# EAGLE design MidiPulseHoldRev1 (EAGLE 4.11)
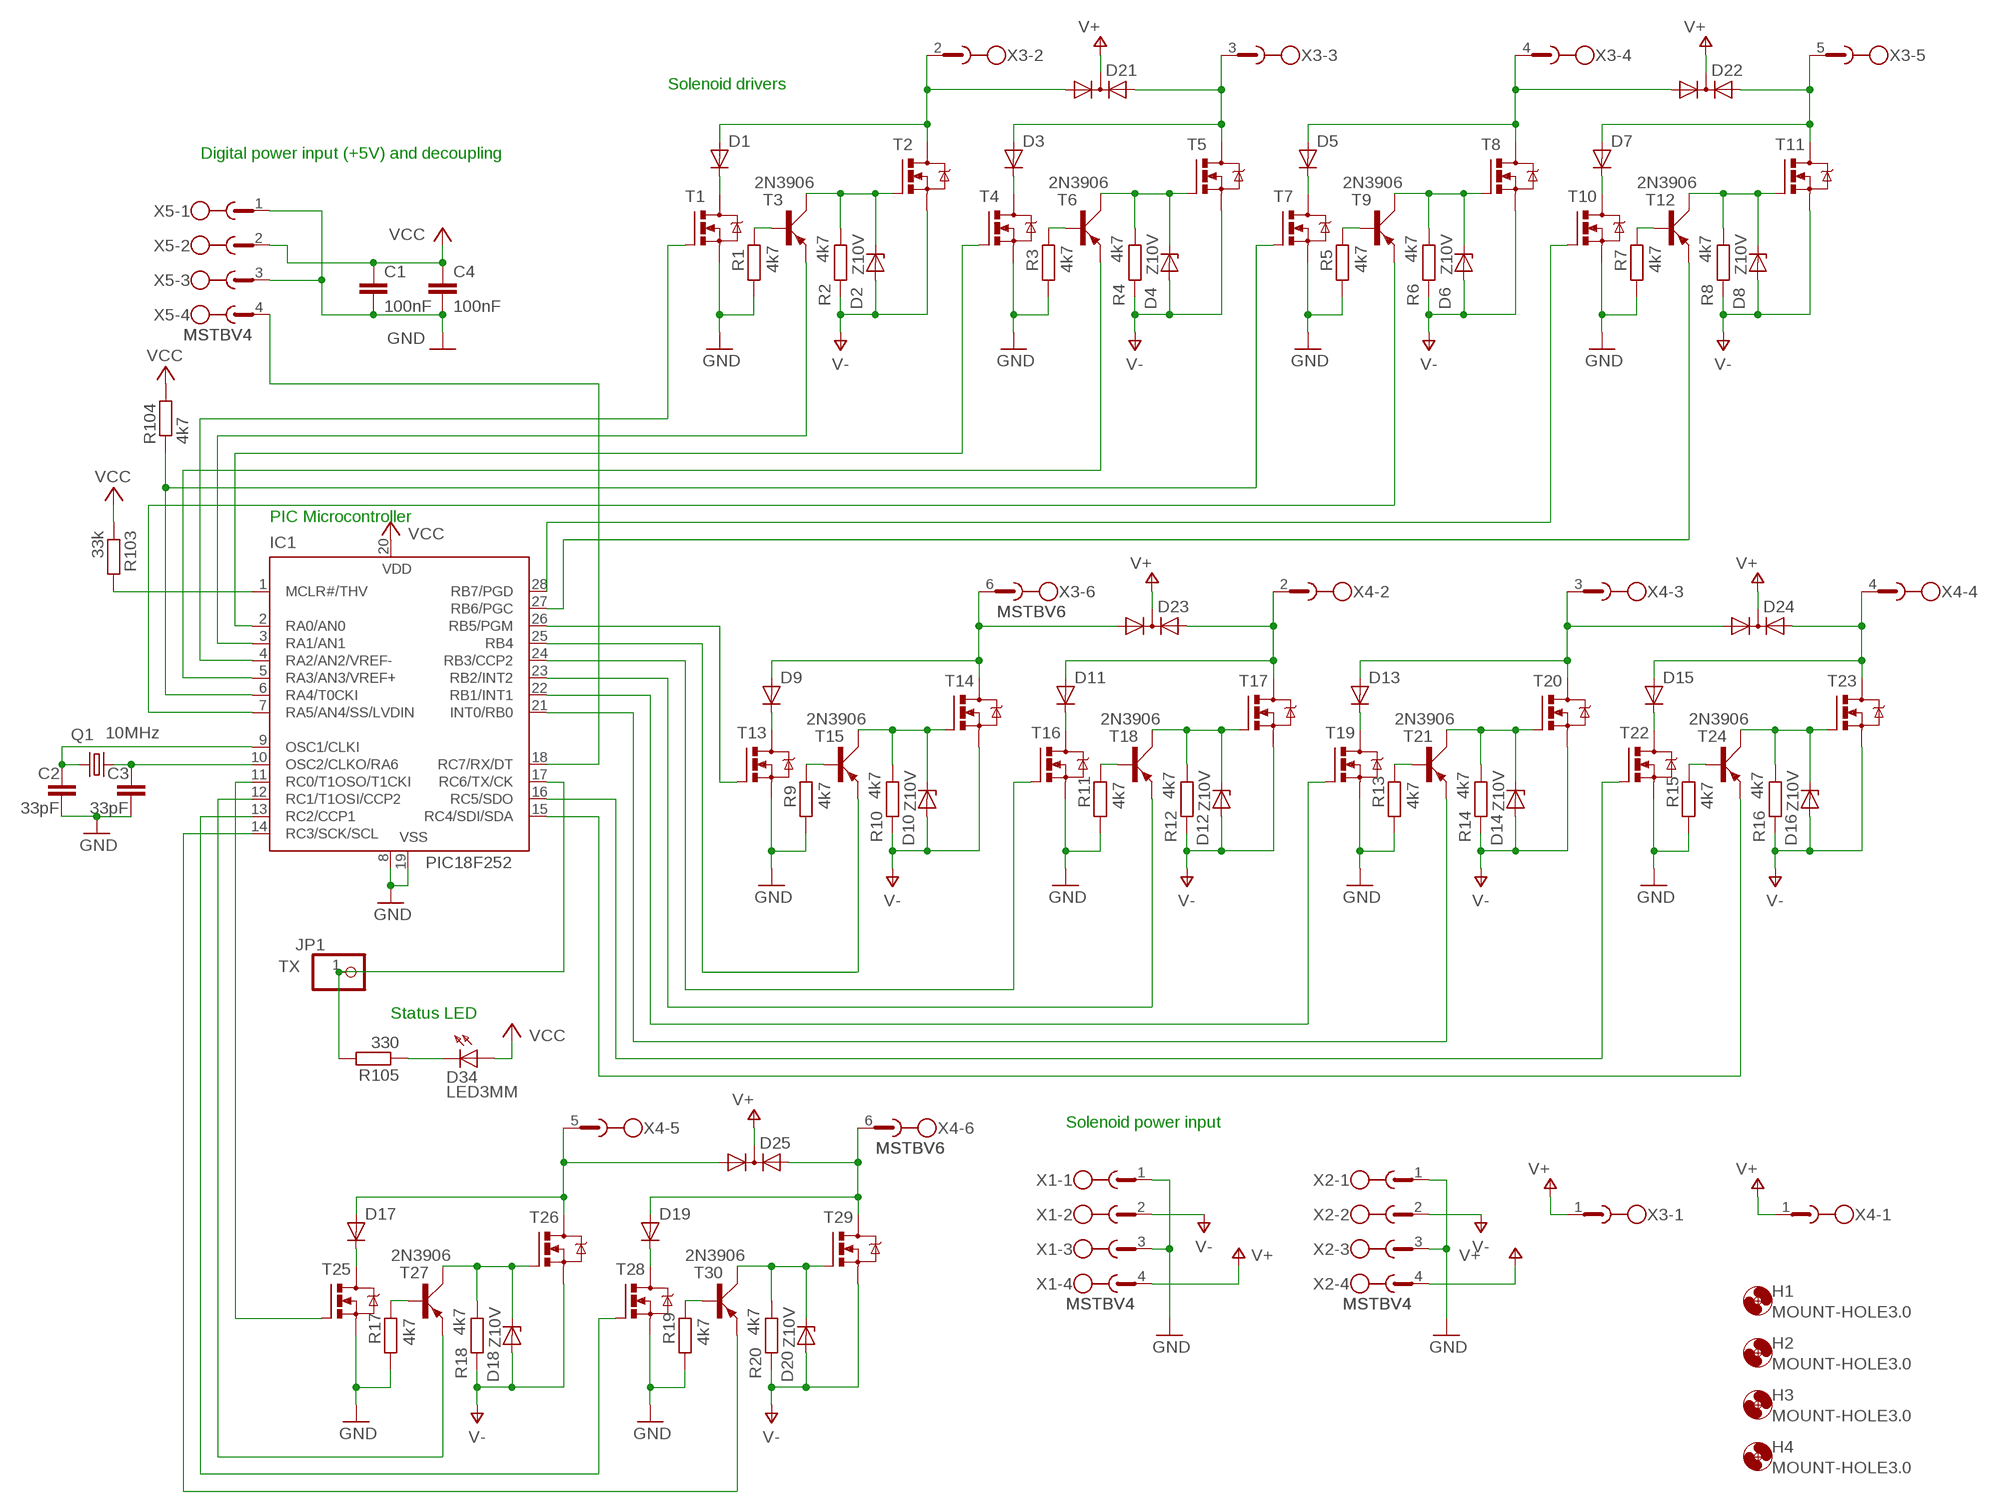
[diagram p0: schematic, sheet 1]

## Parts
C1  100nF  C-EU050-030X075  [C050-030X075]
C2  33pF  C-EU050-025X075  [C050-025X075]
C3  33pF  C-EU050-025X075  [C050-025X075]
C4  100nF  C-EU050-030X075  [C050-030X075]
D1  DIODE-P6-15  [P6-15]
D2  Z10V  ZENER-DIODEDO34-7  [DO34Z7]
D3  DIODE-P6-15  [P6-15]
D4  Z10V  ZENER-DIODEDO34-7  [DO34Z7]
D5  DIODE-P6-15  [P6-15]
D6  Z10V  ZENER-DIODEDO34-7  [DO34Z7]
D7  DIODE-P6-15  [P6-15]
D8  Z10V  ZENER-DIODEDO34-7  [DO34Z7]
D9  DIODE-P6-15  [P6-15]
D10  Z10V  ZENER-DIODEDO34-7  [DO34Z7]
D11  DIODE-P6-15  [P6-15]
D12  Z10V  ZENER-DIODEDO34-7  [DO34Z7]
D13  DIODE-P6-15  [P6-15]
D14  Z10V  ZENER-DIODEDO34-7  [DO34Z7]
D15  DIODE-P6-15  [P6-15]
D16  Z10V  ZENER-DIODEDO34-7  [DO34Z7]
D17  DIODE-P6-15  [P6-15]
D18  Z10V  ZENER-DIODEDO34-7  [DO34Z7]
D19  DIODE-P6-15  [P6-15]
D20  Z10V  ZENER-DIODEDO34-7  [DO34Z7]
D21  DIODE-2AC|CATO220V  [TO220ABS]
D22  DIODE-2AC|CATO220V  [TO220ABS]
D23  DIODE-2AC|CATO220V  [TO220ABS]
D24  DIODE-2AC|CATO220V  [TO220ABS]
D25  DIODE-2AC|CATO220V  [TO220ABS]
D34  LED3MM  [LED3MM]
H1  MOUNT-HOLE3.0  [3,0]
H2  MOUNT-HOLE3.0  [3,0]
H3  MOUNT-HOLE3.0  [3,0]
H4  MOUNT-HOLE3.0  [3,0]
IC1  PIC18F252  [DIL28-3]
JP1  TX  PINHD-1X1  [1X01]
Q1  10MHz  HC49U70  [HC49U70]
R1  4k7  R-EU_0204/7  [0204/7]
R2  4k7  R-EU_0204/7  [0204/7]
R3  4k7  R-EU_0204/7  [0204/7]
R4  4k7  R-EU_0204/7  [0204/7]
R5  4k7  R-EU_0204/7  [0204/7]
R6  4k7  R-EU_0204/7  [0204/7]
R7  4k7  R-EU_0204/7  [0204/7]
R8  4k7  R-EU_0204/7  [0204/7]
R9  4k7  R-EU_0204/7  [0204/7]
R10  4k7  R-EU_0204/7  [0204/7]
R11  4k7  R-EU_0204/7  [0204/7]
R12  4k7  R-EU_0204/7  [0204/7]
R13  4k7  R-EU_0204/7  [0204/7]
R14  4k7  R-EU_0204/7  [0204/7]
R15  4k7  R-EU_0204/7  [0204/7]
R16  4k7  R-EU_0204/7  [0204/7]
R17  4k7  R-EU_0204/7  [0204/7]
R18  4k7  R-EU_0204/7  [0204/7]
R19  4k7  R-EU_0204/7  [0204/7]
R20  4k7  R-EU_0204/7  [0204/7]
R103  33k  R-EU_0207/10  [0207/10]
R104  4k7  R-EU_0207/10  [0207/10]
R105  330  R-EU_0207/7  [0207/7]
T1  IRF520  [TO220BV-ROUND]
T2  IRF520  [TO220BV-ROUND]
T3  2N3906  [TO92D]
T4  IRF520  [TO220BV-ROUND]
T5  IRF520  [TO220BV-ROUND]
T6  2N3906  [TO92D]
T7  IRF520  [TO220BV-ROUND]
T8  IRF520  [TO220BV-ROUND]
T9  2N3906  [TO92D]
T10  IRF520  [TO220BV-ROUND]
T11  IRF520  [TO220BV-ROUND]
T12  2N3906  [TO92D]
T13  IRF520  [TO220BV-ROUND]
T14  IRF520  [TO220BV-ROUND]
T15  2N3906  [TO92D]
T16  IRF520  [TO220BV-ROUND]
T17  IRF520  [TO220BV-ROUND]
T18  2N3906  [TO92D]
T19  IRF520  [TO220BV-ROUND]
T20  IRF520  [TO220BV-ROUND]
T21  2N3906  [TO92D]
T22  IRF520  [TO220BV-ROUND]
T23  IRF520  [TO220BV-ROUND]
T24  2N3906  [TO92D]
T25  IRF520  [TO220BV-ROUND]
T26  IRF520  [TO220BV-ROUND]
T27  2N3906  [TO92D]
T28  IRF520  [TO220BV-ROUND]
T29  IRF520  [TO220BV-ROUND]
T30  2N3906  [TO92D]
X1  MSTBV4  [MSTBV4]
X2  MSTBV4  [MSTBV4]
X3  MSTBV6  [MSTBV6]
X4  MSTBV6  [MSTBV6]
X5  MSTBV4  [MSTBV4]

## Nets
GND: C1.2 C2.2 C3.2 C4.2 IC1.8(VSS) IC1.19(VSS) R1.1 R3.1 R5.1 R7.1 R9.1 R11.1 R13.1 R15.1 R17.1 R19.1 T1.S T4.S T7.S T10.S T13.S T16.S T19.S T22.S T25.S T28.S X1.1 X1.3 X2.1 X2.3 X5.1 X5.3
N$1: D9.A D23.A1 T14.D X3.6
N$2: IC1.25(RB4) T15.E
N$3: C2.1 IC1.9(OSC1/CLKI) Q1.1
N$4: C3.1 IC1.10(OSC2/CLKO/RA6) Q1.2
N$5: IC1.12(RC1/T1OSI/CCP2) T27.E
N$6: IC1.21(INT0/RB0) T21.E
N$7: IC1.1(MCLR#/THV) R103.2
N$8: IC1.15(RC4/SDI/SDA) T24.E
N$9: IC1.22(RB1/INT1) T19.G
N$10: D1.C T1.D
N$11: IC1.16(RC5/SDO) T22.G
N$13: D1.A D21.A1 T2.D X3.2
N$14: R1.2 T3.B
N$15: IC1.3(RA1/AN1) T3.E
N$16: IC1.6(RA4/T0CKI) R104.1 T7.G
N$17: D9.C T13.D
N$18: R9.2 T15.B
N$19: D10.C R10.2 T14.G T15.C
N$20: D3.A D21.A2 T5.D X3.3
N$21: D2.C R2.2 T2.G T3.C
N$22: IC1.4(RA2/AN2/VREF-) T1.G
N$23: IC1.5(RA3/AN3/VREF+) T6.E
N$24: IC1.2(RA0/AN0) T4.G
N$25: IC1.23(RB2/INT2) T18.E
N$26: IC1.24(RB3/CCP2) T16.G
N$27: D3.C T4.D
N$28: IC1.28(RB7/PGD) T10.G
N$29: D11.C T16.D
N$30: R3.2 T6.B
N$31: IC1.7(RA5/AN4/SS/LVDIN) T9.E
N$32: R11.2 T18.B
N$33: D4.C R4.2 T5.G T6.C
N$34: IC1.26(RB5/PGM) T13.G
N$35: D5.C T7.D
N$36: R5.2 T9.B
N$37: IC1.27(RB6/PGC) T12.E
N$38: D6.C R6.2 T8.G T9.C
N$39: D5.A D22.A1 T8.D X3.4
N$40: D34.K(C) R105.1
N$41: D12.C R12.2 T17.G T18.C
N$42: D13.C T19.D
N$43: IC1.11(RC0/T1OSO/T1CKI) T25.G
N$44: D7.C T10.D
N$45: R7.2 T12.B
N$46: IC1.13(RC2/CCP1) T28.G
N$47: D8.C R8.2 T11.G T12.C
N$48: D7.A D22.A2 T11.D X3.5
N$49: D17.C T25.D
N$50: R13.2 T21.B
N$51: D14.C R14.2 T20.G T21.C
N$52: R17.2 T27.B
N$53: D13.A D24.A1 T20.D X4.3
N$54: D15.C T22.D
N$55: D18.C R18.2 T26.G T27.C
N$56: R15.2 T24.B
N$57: D16.C R16.2 T23.G T24.C
N$58: D15.A D24.A2 T23.D X4.4
N$59: D11.A D23.A2 T17.D X4.2
N$60: D17.A D25.A1 T26.D X4.5
N$61: D19.C T28.D
N$62: IC1.18(RC7/RX/DT) X5.4
N$63: R19.2 T30.B
N$65: IC1.17(RC6/TX/CK) JP1.1 R105.2
N$66: IC1.14(RC3/SCK/SCL) T30.E
N$67: D20.C R20.2 T29.G T30.C
N$68: D19.A D25.A2 T29.D X4.6
V+: D21.C D22.C D23.C D24.C D25.C X1.4 X2.4 X3.1 X4.1
V-: D2.A D4.A D6.A D8.A D10.A D12.A D14.A D16.A D18.A D20.A R2.1 R4.1 R6.1 R8.1 R10.1 R12.1 R14.1 R16.1 R18.1 R20.1 T2.S T5.S T8.S T11.S T14.S T17.S T20.S T23.S T26.S T29.S X1.2 X2.2
VCC: C1.1 C4.1 D34.A IC1.20(VDD) R103.1 R104.2 X5.2

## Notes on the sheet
- Solenoid drivers
- Digital power input (+5V) and decoupling
- PIC Microcontroller
- Status LED
- Solenoid power input

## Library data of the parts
C1-C4 = rcl:C-EU: CAPACITOR, European symbol
D1 D3 D5 D7 D9 D11 D13 D15 D17 D19 = diode:DIODE-: DIODE
D2 D4 D6 D8 D10 D12 D14 D16 D18 D20 = diode:ZENER-DIODE: Z-Diode
D21-D25 = diode:DIODE-2AC|CA: Dual DIODE Anode-Cathode|Cathode-Anode
D34 = led:LED3MM: LED
H1-H4 = holes:MOUNT-HOLE: MOUNTING HOLE with drill center marker
IC1 = microchip:PIC18F252
JP1 = pinhead:PINHD-1X1: PIN HEADER
Q1 = crystal:HC49U70: CRYSTAL
R1-R20 R103-R105 = rcl:R-EU_: RESISTOR, European symbol
T1 T2 T4 T5 T7 T8 T10 T11 T13 T14 T16 T17 T19 T20 T22 T23 T25 T26 T28 T29 = transistor-power:IRF520: HEXFET Power MOSFET
T3 T6 T9 T12 T15 T18 T21 T24 T27 T30 = transistor-small-signal:2N3906: PNP TRANSISTOR
X1 X2 X5 = con-phoenix-508:MSTBV4: PHOENIX
X3 X4 = con-phoenix-508:MSTBV6: PHOENIX

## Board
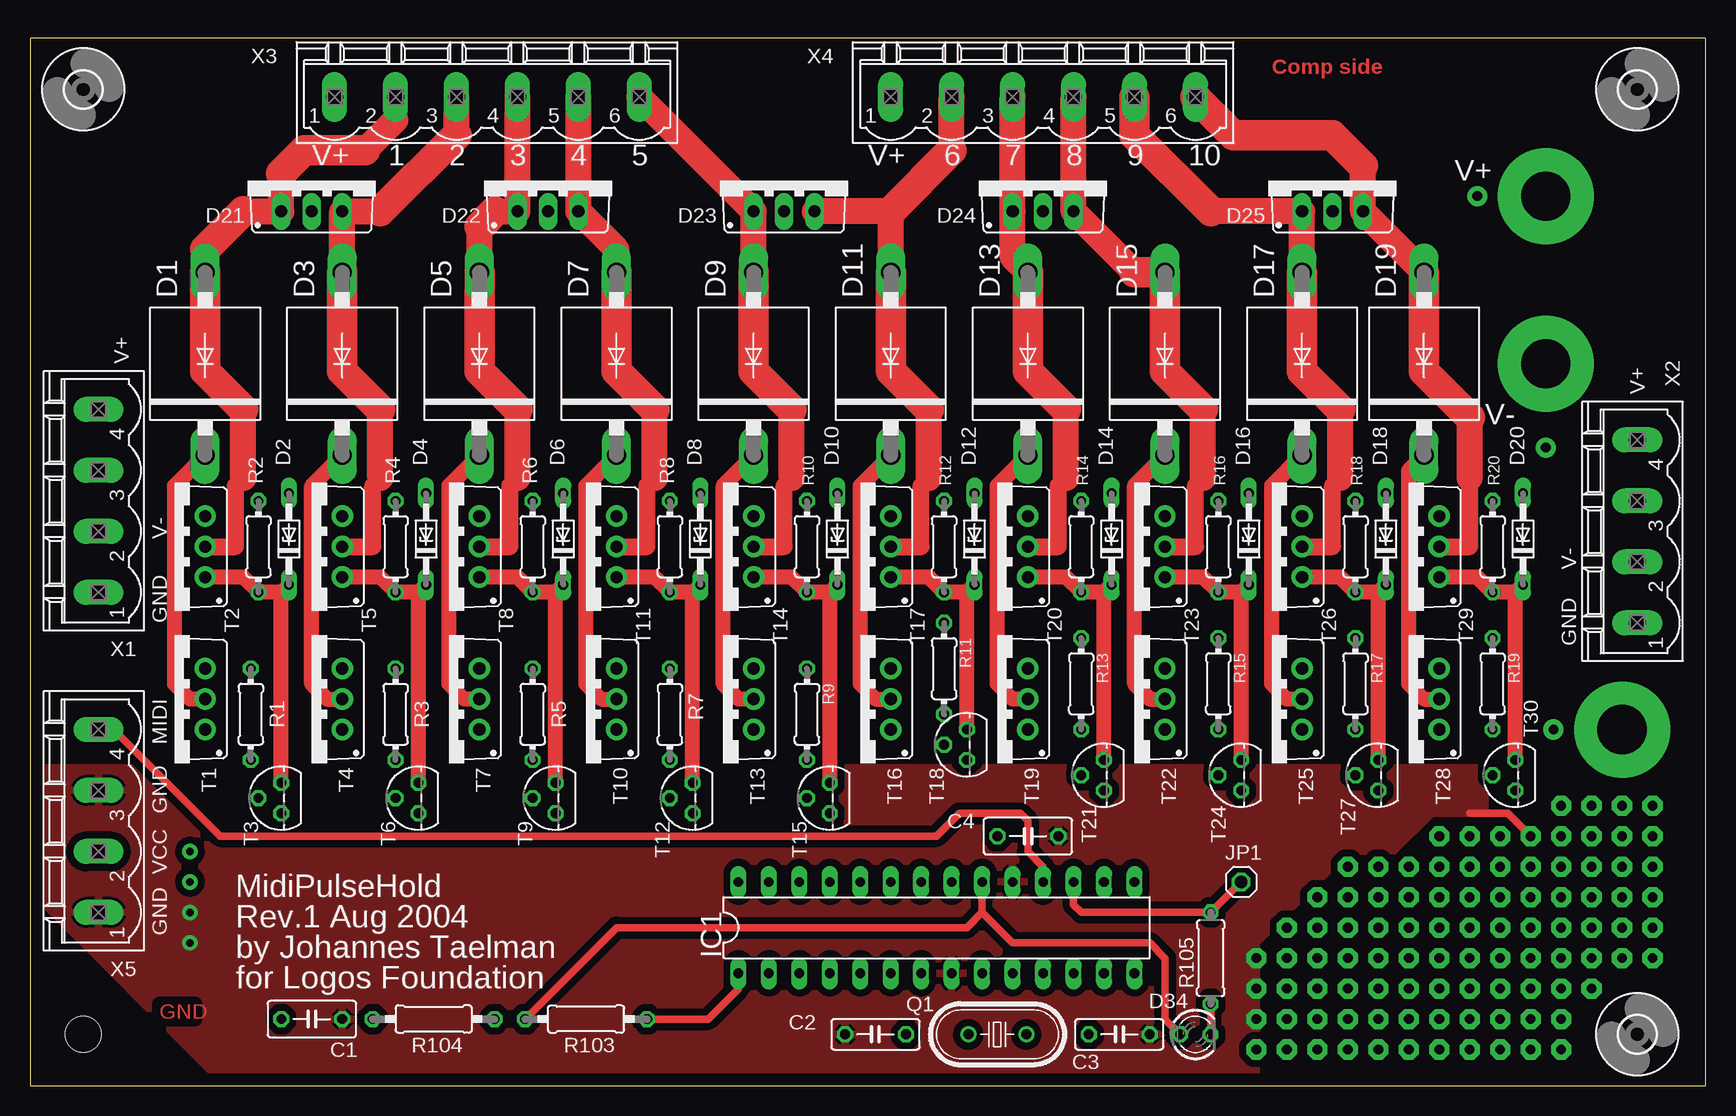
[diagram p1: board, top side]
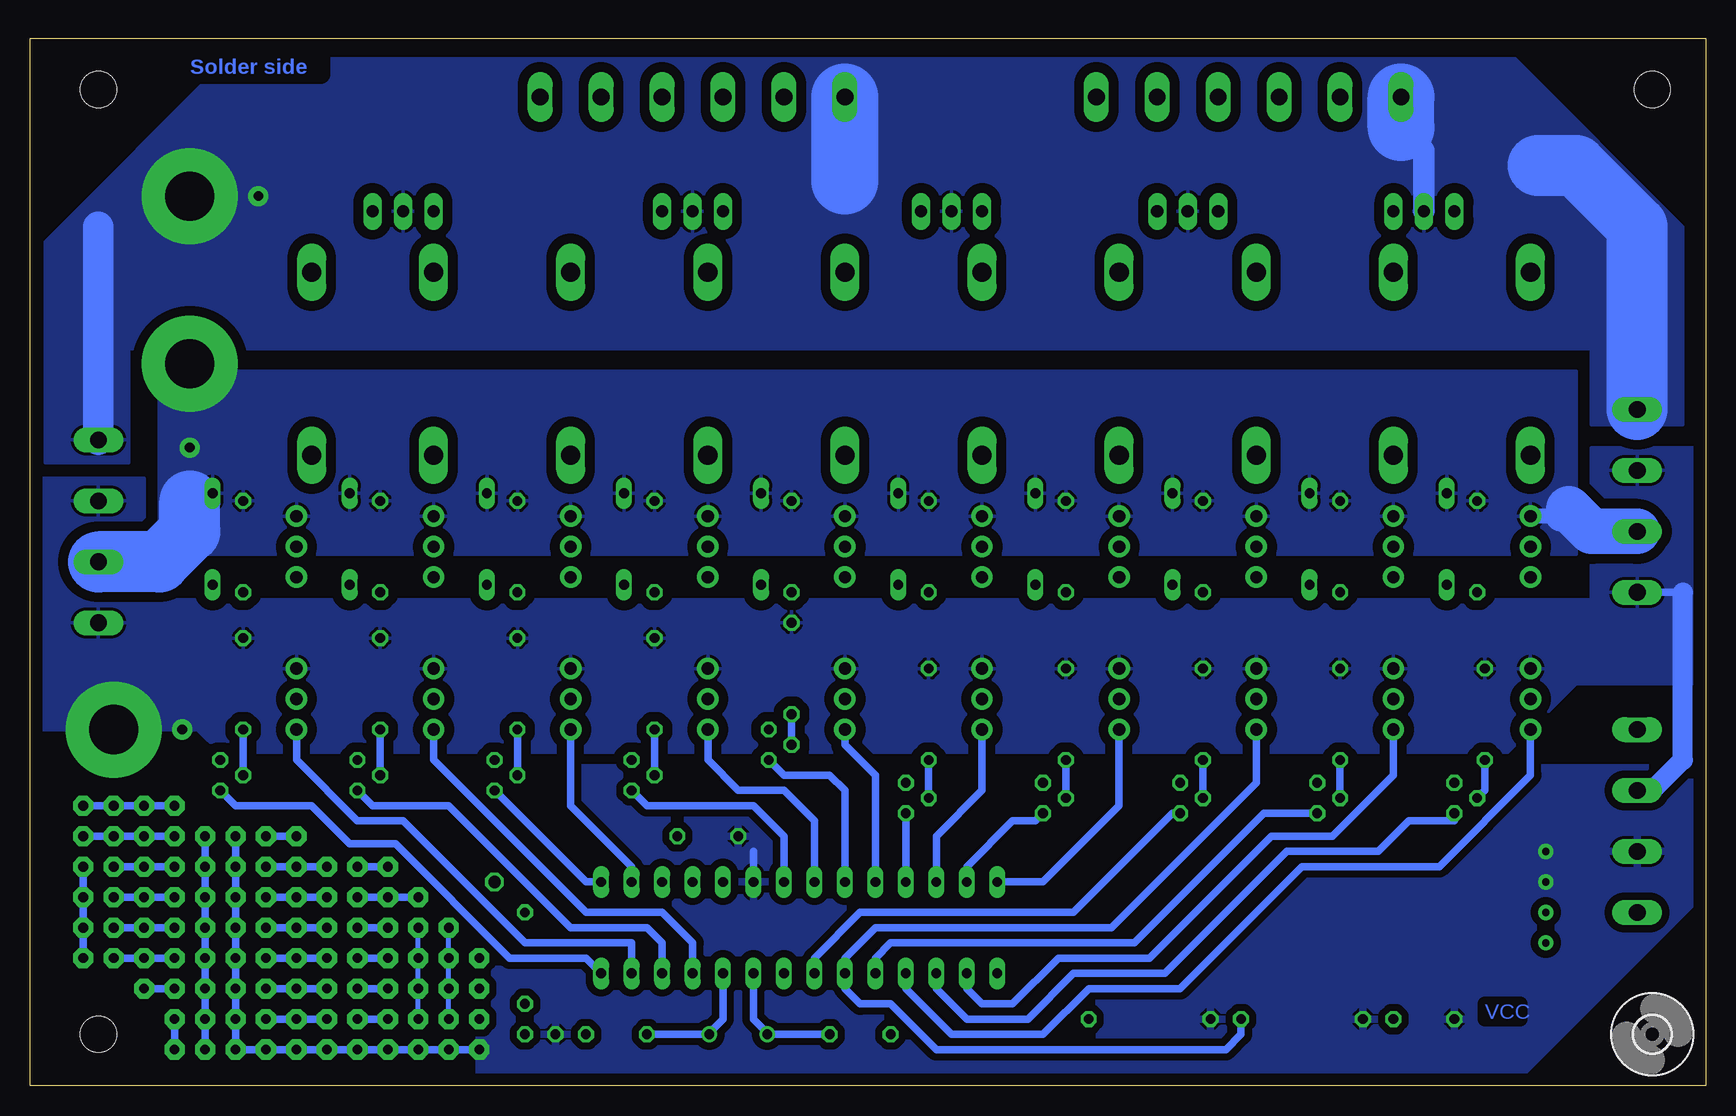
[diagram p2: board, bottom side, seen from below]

Size 139.68 x 87.3 mm. Coordinates in mm from the lower left corner, seen from the top.
Outline: 0,0 139.68,0 139.68,87.3 0,87.3 0,0
Copper layers (1*16): Top 0.035mm / dielectric 1.5mm / Bottom 0.035mm
Design rules "default": minimum track width 10mil, minimum drill 24mil, track to track 8mil, track to pad 8mil, pad to pad 8mil, via to via 8mil, smd to smd 8mil, copper to edge 40mil, drill to drill 8mil, minimum pad ring 10mil, minimum via ring 8mil, stop-mask expansion 0mil, vias tented up to drill 0mil, thermal gap 10mil

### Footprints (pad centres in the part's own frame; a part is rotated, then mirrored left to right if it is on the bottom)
C050-030X075 = drill 0.813 octagon: 1 -2.54,0; 2 2.54,0
C050-025X075 = drill 0.813 octagon: 1 -2.54,0; 2 2.54,0
P6-15 = drill 1.6 long: A 7.62,0; C -7.62,0
DO34Z7 = drill 0.813 long: A 3.81,0; C -3.81,0
TO220ABS = drill 1.016 long: A1 -2.54,-2.54; A2 2.54,-2.54; C 0,-2.54
LED3MM@1 = drill 0.813 octagon: A -1.27,0; K 1.27,0
3,0 = hole 3: 0,0
DIL28-3 = drill 0.813 long: 1 -16.51,-3.81; 2 -13.97,-3.81; 3 -11.43,-3.81; 4 -8.89,-3.81; 5 -6.35,-3.81; 6 -3.81,-3.81; 7 -1.27,-3.81; 8 1.27,-3.81; 9 3.81,-3.81; 10 6.35,-3.81; 11 8.89,-3.81; 12 11.43,-3.81; 13 13.97,-3.81; 14 16.51,-3.81; 15 16.51,3.81; 16 13.97,3.81; 17 11.43,3.81; 18 8.89,3.81; 19 6.35,3.81; 20 3.81,3.81; 21 1.27,3.81; 22 -1.27,3.81; 23 -3.81,3.81; 24 -6.35,3.81; 25 -8.89,3.81; 26 -11.43,3.81; 27 -13.97,3.81; 28 -16.51,3.81
1X01 = drill 1.016 octagon: 1 0,0
HC49U70@1 = drill 0.813 round: 1 -2.413,0; 2 2.413,0
0204/7 = drill 0.813 octagon: 1 -3.81,0; 2 3.81,0
0207/10 = drill 0.813 octagon: 1 -5.08,0; 2 5.08,0
0207/7 = drill 0.813 octagon: 1 -3.81,0; 2 3.81,0
TO220BV-ROUND = drill 1.016 pad 1.778 round: D 0,-2.54; G -2.54,-2.54; S 2.54,-2.54
TO92D = drill 0.813 octagon: B 0,1.905; C 1.27,0; E -1.27,0
MSTBV4 = drill 1.397 long: 1 -7.62,0; 2 -2.54,0; 3 2.54,0; 4 7.62,0
MSTBV6 = drill 1.397 long: 1 -12.7,0; 2 -7.62,0; 3 -2.54,0; 4 2.54,0; 5 7.62,0; 6 12.7,0

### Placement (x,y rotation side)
C1  23.49,5.55 0 top
C2  70.48,4.28 180 top
C3  90.8,4.28 0 top
C4  83.18,20.79 0 top
D1  14.6,60.16 90 top
D2  21.58,45.55 90 top
D3  26.03,60.16 90 top
D4  33.02,45.55 90 top
D5  37.46,60.16 90 top
D6  44.45,45.55 90 top
D7  48.89,60.16 90 top
D8  55.88,45.55 90 top
D9  60.32,60.16 90 top
D10  67.3,45.55 90 top
D11  71.75,60.16 90 top
D12  78.73,45.55 90 top
D13  83.18,60.16 90 top
D14  90.16,45.55 90 top
D15  94.61,60.16 90 top
D16  101.59,45.55 90 top
D17  106.04,60.16 90 top
D18  113.02,45.55 90 top
D19  116.2,60.16 90 top
D20  124.45,45.55 90 top
D21  23.49,75.4 0 top
D22  43.18,75.4 0 top
D23  62.86,75.4 0 top
D24  84.45,75.4 0 top
D25  108.58,75.4 0 top
D34  LED3MM  [LED3MM@1]  97.15,4.28 0 top
H1  4.44,4.28 0 bottom
H2  133.98,4.28 0 top
H3  133.98,83.02 0 top
H4  4.44,83.02 0 top
IC1  75.56,13.17 0 top
JP1  100.96,16.98 0 top
Q1  10MHz  [HC49U70@1]  80.64,4.28 0 top
R1  18.41,30.95 270 top
R2  19.04,44.92 270 top
R3  30.47,30.95 270 top
R4  30.47,44.92 270 top
R5  41.91,30.95 270 top
R6  41.91,44.92 270 top
R7  53.34,30.95 270 top
R8  53.34,44.92 270 top
R9  64.77,30.95 270 top
R10  64.77,44.92 270 top
R11  76.19,34.76 270 top
R12  76.19,44.92 270 top
R13  87.62,33.49 270 top
R14  87.62,44.92 270 top
R15  99.05,33.49 270 top
R16  99.05,44.92 270 top
R17  110.48,33.49 270 top
R18  110.48,44.92 270 top
R19  121.91,33.49 270 top
R20  121.91,44.92 270 top
R103  46.35,5.55 0 top
R104  33.65,5.55 180 top
R105  98.42,10.63 90 top
T1  12.06,32.22 90 top
T2  12.06,44.92 90 top
T3  20.95,23.96 90 top
T4  23.49,32.22 90 top
T5  23.49,44.92 90 top
T6  32.38,23.96 90 top
T7  34.92,32.22 90 top
T8  34.92,44.92 90 top
T9  43.81,23.96 90 top
T10  46.35,32.22 90 top
T11  46.35,44.92 90 top
T12  55.24,23.96 90 top
T13  57.78,32.22 90 top
T14  57.78,44.92 90 top
T15  66.67,23.96 90 top
T16  69.21,32.22 90 top
T17  69.21,44.92 90 top
T18  78.1,28.41 90 top
T19  80.64,32.22 90 top
T20  80.64,44.92 90 top
T21  89.53,25.87 90 top
T22  92.07,32.22 90 top
T23  92.07,44.92 90 top
T24  100.96,25.87 90 top
T25  103.5,32.22 90 top
T26  103.5,44.92 90 top
T27  112.39,25.87 90 top
T28  114.93,32.22 90 top
T29  114.93,44.92 90 top
T30  123.82,25.87 90 top
X1  5.71,48.73 90 top
X2  133.98,46.19 90 top
X3  38.1,82.39 0 top
X4  84.45,82.39 0 top
X5  5.71,22.06 90 top

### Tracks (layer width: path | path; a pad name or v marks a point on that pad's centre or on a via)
GND  (via drill 0.61 pad 1.27, 0.81 pad 1.68, 4.1 pad 8)
  Top 0.61: v125.09,20.79 123.19,22.7 120.01,22.7
  Bottom 0.61: 4.44,24.6 X5.3 | 1.9,41.11 X1.1 | v125.09,20.79 v125.09,18.25 v125.09,15.71 v125.09,13.17 v125.09,10.63 v125.09,8.09 v125.09,5.55 v125.09,3.01
  Bottom 1.676: 4.44,24.6 1.9,27.14 1.9,41.11
  other vias: 132.71,29.68 126.99,29.68 102.23,8.09 102.23,5.55 102.23,10.63 13.33,14.44 13.33,11.9
  pour Top (isolate 0.61): 0.63,26.5 121.28,26.5 121.28,22.7 116.83,22.7 113.66,19.52 109.85,19.52 102.23,11.9 102.23,0.47 15.87,0.47 0.63,15.71
  pour Bottom (isolate 0.813): -0.64,33.49 -0.64,53.17 9.52,53.17 9.52,40.48 130.17,40.48 130.17,50.63 139.06,50.63 139.06,29.68 125.72,29.68 123.82,27.77 16.5,27.77 10.79,33.49
N$1
  Top 1.27: 62.86,50 63.5,50.63
  Top 1.422: T14.D 62.86,44.92 62.86,50
  Top 2.184: 63.5,50.63 63.5,56.35 | D9.A D23.A1 X3.6
  Top 2.54: 63.5,56.35 60.32,59.52 D9.A
N$2
  Bottom 0.61: IC1.25 T15.E
N$3
  Bottom 0.61: 78.1,4.28 79.37,5.55 IC1.9 | C2.1 78.1,4.28 | 78.1,4.28 Q1.1
N$4
  Bottom 0.61: 83.18,4.28 Q1.2 83.05,4.41 83.18,4.28 | 83.18,4.28 81.91,5.55 IC1.10 | 83.18,4.28 C3.1
N$5
  Bottom 0.61: IC1.12 86.99,11.9 88.26,13.17 94.61,13.17 104.77,23.33 111.12,23.33 T27.E
N$6
  Bottom 0.61: IC1.21 76.83,20.79 79.37,23.33 88.26,23.33 T21.E
N$7
  Top 0.61: R103.2 56.51,5.55 59.05,8.09 IC1.1
N$8
  Bottom 0.61: IC1.15 93.34,16.98 T24.E
N$9
  Bottom 0.61: IC1.22 74.29,22.06 76.83,24.6 80.64,24.6 83.18,27.14 T19.G
N$10
  Top 1.27: T1.D 13.33,32.22 12.06,33.49 12.06,50 D1.C
N$11
  Bottom 0.61: IC1.16 89.53,18.25 94.61,23.33 T22.G
N$13
  Top 1.27: 17.14,50 17.77,50.63
  Top 1.422: 17.14,50 17.14,44.92 T2.D
  Top 1.676: 30.47,80.48 X3.2
  Top 2.184: 17.77,50.63 17.77,56.35 | D1.A 14.6,69.69 | 17.77,72.86 D21.A1 20.95,76.03 | 27.93,77.94 30.47,80.48
  Top 2.54: 17.77,56.35 14.6,59.52 D1.A | 14.6,69.69 17.77,72.86 | 20.95,76.03 22.86,77.94 27.93,77.94
N$14
  Bottom 0.61: T3.B 18.41,24.6 R1.2
N$15
  Bottom 0.61: IC1.3 64.13,8.09 61.59,5.55 56.51,5.55 52.7,9.36 45.08,9.36 34.92,19.52 27.3,19.52 24.76,22.06 20.95,22.06 T3.E
N$16
  Bottom 0.61: R104.1 38.73,4.28 40,3.01 64.13,3.01 67.94,6.82 70.48,6.82 71.75,8.09 IC1.6 71.75,10.63 69.21,13.17 49.53,13.17 37.46,25.23 T7.G
N$17
  Top 1.27: D9.C 57.78,50 57.78,33.49 59.05,32.22 T13.D
N$18
  Bottom 0.61: T15.B R9.2
N$19
  Top 1.27: T14.G 63.5,42.38 R10.2 66.67,41.11 | T15.C 66.67,41.11 | 66.67,41.11 D10.C
N$20
  Top 1.422: 29.2,50.63 28.57,50 28.57,44.92 T5.D
  Top 2.184: 29.2,50.63 29.2,56.35 | D3.A D21.A2 29.2,72.86 | 35.55,79.21 X3.3
  Top 2.54: D3.A 26.03,59.52 29.2,56.35 | 29.2,72.86 35.55,79.21
N$21
  Top 1.27: 20.95,41.11 D2.C 20.95,41.11 | 20.95,41.11 R2.2 17.77,42.38 T2.G | T3.C 20.95,41.11
N$22
  Bottom 0.61: IC1.4 66.67,8.09 62.86,4.28 55.24,4.28 51.43,8.09 43.81,8.09 33.65,18.25 22.22,18.25 14.6,25.87 T1.G
N$23
  Bottom 0.61: IC1.5 69.21,10.63 67.94,11.9 47.62,11.9 36.83,22.7 T6.E
N$24
  Bottom 0.61: IC1.2 61.59,8.09 60.32,6.82 57.78,6.82 53.97,10.63 46.35,10.63 36.19,20.79 31.11,20.79 26.03,25.87 T4.G
N$25
  Bottom 0.61: IC1.23 71.75,24.6 73.02,25.87 76.83,25.87 T18.E
N$26
  Bottom 0.61: IC1.24 69.21,25.87 71.75,28.41 T16.G
N$27
  Top 1.27: T4.D 24.76,32.22 23.49,33.49 23.49,50 D3.C
N$28
  Bottom 0.61: IC1.28 55.24,16.98 48.89,23.33 T10.G
N$29
  Top 1.27: D11.C 69.21,50 69.21,33.49 70.48,32.22 T16.D
N$30
  Bottom 0.61: T6.B R3.2
N$31
  Bottom 0.61: IC1.7 74.29,10.63 70.48,14.44 52.7,14.44 44.45,22.7 T9.E
N$32
  Bottom 0.61: T18.B R11.2
N$33
  Top 1.27: 32.38,41.11 D4.C 32.38,41.11 | 32.38,41.11 R4.2 29.2,42.38 T5.G | T6.C 32.38,41.11
N$34
  Bottom 0.61: IC1.26 64.13,20.79 60.32,24.6 T13.G
N$35
  Top 1.27: D5.C 34.92,50 34.92,33.49 36.19,32.22 T7.D
N$36
  Bottom 0.61: T9.B R5.2
N$37
  Bottom 0.61: IC1.27 61.59,18.25 57.78,22.06 55.88,22.06 T12.E
N$38
  Top 1.27: 43.81,41.11 R6.2 40.64,42.38 T8.G | T9.C 43.81,41.11 | 43.81,41.11 D6.C
N$39
  Top 1.422: T8.D 40,44.92 40,50 40.64,50.63
  Top 2.184: 40.64,50.63 40.64,56.35 | D5.A 37.46,71.59 | 38.73,72.86 D22.A1 X3.4
  Top 2.54: 40.64,56.35 37.46,59.52 D5.A | 37.46,71.59 38.73,72.86
N$40
  Top 0.61: D34.K R105.1
N$41
  Top 1.27: T17.G 74.92,42.38 R12.2 78.1,41.11 | T18.C 78.1,41.11 | 78.1,41.11 D12.C
N$42
  Top 1.27: D13.C 80.64,50 80.64,33.49 81.91,32.22 T19.D
N$43
  Bottom 0.61: IC1.11 84.45,11.9 86.99,14.44 93.34,14.44 106.04,27.14 T25.G
N$44
  Top 1.27: D7.C 46.35,50 46.35,33.49 47.62,32.22 T10.D
N$45
  Bottom 0.61: T12.B R7.2
N$46
  Bottom 0.61: IC1.13 89.53,11.9 98.42,11.9 108.58,22.06 112.39,22.06 117.47,27.14 T28.G
N$47
  Top 1.27: 55.24,41.11 D8.C 55.24,41.11 | 55.24,41.11 R8.2 52.07,42.38 T11.G | T12.C 55.24,41.11
N$48
  Top 1.016: D7.A 48.89,69.69
  Top 1.422: T11.D 51.43,44.92 51.43,50 52.07,50.63
  Top 2.184: 52.07,50.63 52.07,56.35 | X3.5 D22.A2 48.89,69.69
  Top 2.54: 52.07,56.35 48.89,59.52 D7.A
N$49
  Top 1.27: T25.D 104.77,32.22 103.5,33.49 103.5,50 D17.C
N$50
  Bottom 0.61: T21.B R13.2
N$51
  Top 1.016: 89.53,41.11 D14.C
  Top 1.27: T20.G 86.35,42.38 R14.2 89.53,41.11 | T21.C 89.53,41.11 | 89.53,41.11 D14.C
N$52
  Bottom 0.61: T27.B R17.2
N$53
  Top 1.27: 85.72,50 86.35,50.63
  Top 1.422: T20.D 85.72,44.92 85.72,50
  Top 2.184: D13.A 81.91,69.05 D24.A1 X4.3 | 86.35,50.63 86.35,56.35
  Top 2.54: 86.35,56.35 83.18,59.52 D13.A
N$54
  Top 1.27: D15.C 92.07,50 92.07,33.49 93.34,32.22 T22.D
N$55
  Top 1.27: T26.G 109.21,42.38 R18.2 112.39,41.11 | T27.C 112.39,41.11 | 112.39,41.11 D18.C
N$56
  Bottom 0.61: T24.B R15.2
N$57
  Top 1.27: T23.G 97.78,42.38 R16.2 100.96,41.11 | T24.C 100.96,41.11 | 100.96,41.11 D16.C
N$58
  Top 1.27: 97.15,50 97.78,50.63
  Top 1.422: T23.D 97.15,44.92 97.15,50
  Top 2.184: 97.78,50.63 97.78,56.35 | X4.4 D24.A2 92.07,67.78
  Top 2.54: 92.07,67.78 D15.A 94.61,59.52 97.78,56.35
N$59
  Top 1.27: 74.29,50 74.92,50.63
  Top 1.422: T17.D 74.29,44.92 74.29,50
  Top 2.184: 74.92,50.63 74.92,56.35 | D11.A 71.75,72.86 D23.A2 | 76.83,77.94 X4.2
  Top 2.54: 74.92,56.35 71.75,59.52 D11.A | 71.75,72.86 76.83,77.94
N$60
  Top 1.27: 108.58,50 109.21,50.63
  Top 1.422: T26.D 108.58,44.92 108.58,50
  Top 2.184: 109.21,50.63 109.21,56.35 | D17.A D25.A1 98.42,72.86
  Top 2.54: 109.21,56.35 106.04,59.52 D17.A | 98.42,72.86 92.07,79.21 X4.5
N$61
  Top 1.27: T28.D 116.2,32.22 114.93,33.49 114.93,51.27 D19.C
N$62
  Top 0.61: X5.4 6.98,29.68 15.87,20.79 75.56,20.79 77.46,22.7 82.55,22.7 83.18,22.06 83.18,19.52 84.45,18.25 IC1.18
N$63
  Bottom 0.61: T30.B R19.2
N$64  (via drill 0.81 pad 1.68)
  Bottom 0.61: v127.63,8.09 v130.17,8.09
N$65
  Top 0.61: IC1.17 86.99,15.08 87.62,14.44 R105.2 JP1.1
N$66
  Bottom 0.61: IC1.14 93.34,10.63 99.69,10.63 109.21,20.15 113.02,20.15 116.2,23.33 122.55,23.33 T30.E
N$67
  Top 1.27: T29.G 120.64,42.38 R20.2 123.82,41.11 | T30.C 123.82,41.11 | 123.82,41.11 D20.C
N$68
  Top 1.422: T29.D 120.01,44.92 120.01,50.63
  Top 2.184: 120.01,50.63 120.01,55.71 | 111.12,76.67 D25.A2 D19.A
  Top 2.54: 120.01,55.71 116.2,59.52 D19.A | 111.12,76.67 108.58,79.21 100.32,79.21 X4.6
N$69  (via drill 0.81 pad 1.68)
  Bottom 0.61: v109.85,18.25 v112.39,18.25
N$70  (via drill 0.81 pad 1.68)
  Bottom 0.61: v117.47,20.79 v120.01,20.79
N$71  (via drill 0.81 pad 1.68)
  Bottom 0.61: v127.63,23.33 v130.17,23.33 v132.71,23.33 v135.25,23.33
N$72  (via drill 0.81 pad 1.68)
  Bottom 0.61: v120.01,18.25 v117.47,18.25 v114.93,18.25
N$74  (via drill 0.81 pad 1.68)
  Bottom 0.61: v127.63,20.79 v130.17,20.79 v132.71,20.79 v135.25,20.79
N$79  (via drill 0.81 pad 1.68)
  Bottom 0.61: v135.25,18.25 v135.25,15.71 v135.25,13.17 v135.25,10.63
N$81  (via drill 0.81 pad 1.68)
  Bottom 0.61: v127.63,18.25 v130.17,18.25 v132.71,18.25
N$84  (via drill 0.81 pad 1.68)
  Bottom 0.61: v127.63,15.71 v130.17,15.71 v132.71,15.71
N$89  (via drill 0.81 pad 1.68)
  Bottom 0.61: v127.63,13.17 v130.17,13.17 v132.71,13.17
N$96  (via drill 0.81 pad 1.68)
  Bottom 0.61: v127.63,10.63 v130.17,10.63 v132.71,10.63
N$97  (via drill 0.81 pad 1.68)
  Bottom 0.61: v112.39,15.71 v109.85,15.71 v107.31,15.71
N$98  (via drill 0.81 pad 1.68)
  Bottom 0.61: v127.63,3.01 v127.63,5.55
N$99  (via drill 0.81 pad 1.68)
  Bottom 0.61: v109.85,13.17 v112.39,13.17
N$102  (via drill 0.81 pad 1.68)
  Bottom 0.406: v107.31,13.17 v107.31,10.63 v107.31,8.09 v107.31,5.55
N$118  (via drill 0.81 pad 1.68)
  Bottom 0.61: v120.01,5.55 v117.47,5.55 v114.93,5.55
N$121  (via drill 0.81 pad 1.68)
  Bottom 0.61: v120.01,8.09 v117.47,8.09 v114.93,8.09
N$124  (via drill 0.81 pad 1.68)
  Bottom 0.61: v120.01,10.63 v117.47,10.63 v114.93,10.63
N$125  (via drill 0.81 pad 1.68)
  Bottom 0.61: v120.01,13.17 v117.47,13.17 v114.93,13.17
N$130  (via drill 0.81 pad 1.68)
  Bottom 0.61: v109.85,5.55 v112.39,5.55
N$131  (via drill 0.81 pad 1.68)
  Bottom 0.61: v109.85,8.09 v112.39,8.09
N$139  (via drill 0.81 pad 1.68)
  Bottom 0.406: v104.77,5.55 v104.77,8.09 v104.77,10.63 v104.77,13.17
N$142  (via drill 0.81 pad 1.68)
  Bottom 0.61: v109.85,10.63 v112.39,10.63
N$147  (via drill 0.81 pad 1.68)
  Bottom 0.61: v120.01,15.71 v117.47,15.71 v114.93,15.71
V+  (via drill 0.81 pad 1.68, 4.1 pad 8)
  Bottom 1.778: 25.39,79.84 23.49,77.94 D21.C
  Bottom 2.54: X2.4 133.98,71.59
  Bottom 5.08: X1.4 5.71,71.59 10.79,76.67 13.97,76.67
  Bottom 5.588: 25.39,79.84 X3.1 | 71.75,75.4 X4.1
  other vias: 126.36,74.13 120.64,74.13
  pour Bottom (isolate 0.813): 15.87,85.56 123.19,85.56 138.42,70.32 138.42,51.91 131.44,51.91 131.44,61.43 9.52,61.43 9.52,55.08 1.9,55.08 1.9,71.59
V-  (via drill 0.81 pad 1.68, 4.1 pad 8)
  Bottom 1.27: 12.06,47.46 T2.S
  Bottom 2.54: 11.43,48.09 12.06,47.46
  Bottom 3.81: X1.2 9.52,46.19 11.43,48.09
  Bottom 5.08: 126.36,48.73 126.36,46.19 128.9,43.65 X2.2
  other vias: 126.36,60.16 126.36,53.17
  pour Bottom (isolate 0.813): 10.79,59.52 128.9,59.52 128.9,44.28 10.79,44.28
VCC  (via drill 0.61 pad 1.27, 0.81 pad 1.68)
  Top 0.61: 79.37,14.44 78.1,13.17 48.89,13.17 R103.1 | 79.37,14.44 IC1.20 | D34.A 94.61,5.55 94.61,10.63 93.34,11.9 81.91,11.9 79.37,14.44
  Bottom 0.61: IC1.20 79.37,19.52 | v122.55,20.79 v122.55,18.25 v122.55,15.71 v122.55,13.17 v122.55,10.63 v122.55,8.09 v122.55,5.55 v122.55,3.01 v120.01,3.01 v117.47,3.01 v114.93,3.01 v112.39,3.01 v109.85,3.01 v107.31,3.01 v104.77,3.01 v102.23,3.01
  other vias: 13.33,19.52 13.33,16.98
  pour Bottom (isolate 0.61): -1.91,26.5 102.23,26.5 102.23,-2.07 18.41,-2.07 -1.91,18.25

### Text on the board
Top: Comp side | GND
Bottom: Solder side | VCC
tNames: V+ | 1 | 2 | 3 | 4 | 5 | V+ | 6 | 7 | 8 | 9 | 10 | V+ | V+ | V+ | V- | V- | V- | GND | GND | MIDI | GND | VCC | MidiPulseHold | Rev.1 Aug 2004 | GND | by Johannes Taelman | for Logos Foundation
